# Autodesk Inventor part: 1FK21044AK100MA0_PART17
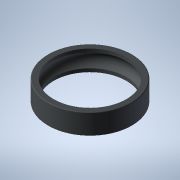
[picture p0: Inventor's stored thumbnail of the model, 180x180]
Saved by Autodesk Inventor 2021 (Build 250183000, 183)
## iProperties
Created: 2025-04
Part Number: 1FK21044AK100MA0_PART17
Material: Generic
Catalog Web Link: www.3dfindit.com
Description: -Servo synchronous motor
Document SubType Name: Modeling
Designer: psAdmin
Mass: 1.64389 g
Surface Area: 26.4305 cm^2
Volume: 1.64389 cm^3
Density: 1 g/cm^3
Appearance: PSOLRGB-212-217-219
Category: PARTsolutions
Title: 1FK21044AK100MA0_PART17
Author: Cadenas PARTsolutions
Comments: Servo synchronous motor
Sending System: PARTsolutions
Preprocessor: ST-DEVELOPER v19.3
PSOL_IDENT_0: {$CADENAS_DATA/23d-libs/siemens_ag/_cat_/5e/d8/1fk21044ak100ma0.prj},216 {VTYP=3D},{NB=1FK21044AK100
PSOL_IDENT_1: MA0_PART17},{LINA=1FK21044AK100MA0_PART17},{NN=1FK21044AK100MA0_PART17},{NOPRJ=TRUE},{DATE=19.08.202
PSOL_IDENT_2: 5 14:00:41},{GEOMDATE=30.07.2025 02:00:53},{VERSION=},{LINEID=10},{WBVAR=},{WBNUMERIC=}  {NB=1FK2104
PSOL_IDENT_3: 4AK100MA0_PART17},{LINA=1FK21044AK100MA0_PART17},{KT=DUMMY},{PREVIEW=../../../_pool_/cb/72/p_d211_xx
PSOL_IDENT_4: _00434j.png},{DESCSHORT=SIMOTICS S-1FK2 HD, SINAMICS S210 3AC 400V-480V, 0.95 Nm, 6000 rpm},{DESCLON
PSOL_IDENT_5: G=SIMOTICS S-1FK2 HD servo motor M0=1.27 Nm; PN = 0.6 kW at nN=6000 rpm (380-480 V); PN = 0.4 kW at
PSOL_IDENT_6: nN=3000 rpm (200-240 V); with holding brake; degree of protection IP64; cylindrical shaft D19x40mm;
PSOL_IDENT_7: absolute encoder 22-bit + 12-bit multiturn (encoder AM22DQC); with OCC interface; plug size M17, rot
PSOL_IDENT_8: atable; SIMOTICS S-1FK2 servomotorfor a wide range of uses in industrial environments. SIMOTICS S‑1F
PSOL_IDENT_9: K2 servomotors are compact synchronous motors with a high dynamic performance that set themselves ap
PSOL_IDENT_10: art as a result of their high power density, degree of protection and overload capability. The motor
PSOL_IDENT_11: s are available in two variants: as High Dynamic variant (highest dynamic performance as a result of
PSOL_IDENT_12: the low intrinsic moment of inertia for applications demanding a high dynamic performance with low
PSOL_IDENT_13: moved masses) - and as Compact variant (precise and stable closed-loop control for medium up to larg
PSOL_IDENT_14: e moved masses as a result of a medium intrinsic moment of inertia). SIMOTICSS‑1FK2 servomotors full
PSOL_IDENT_15: y exploit their strengths in a system with the SINAMICSS210 frequency converter and simple connectio
PSOL_IDENT_16: n using the one cable connection (OCC). Advantages include the short control and positioning times,
PSOL_IDENT_17: fast and precise correction of disturbing quantities as well as stable control with a high dynamic p
PSOL_IDENT_18: erformance. The servo motors can be configured to address a wide range of requirements. For example
PSOL_IDENT_19: with and without holding brake, IP64 or IP65 degree of protection, singleturn or multiturn absolute
PSOL_IDENT_20: encoders - to name just a few. Further, the servomotors are available in different shaft heights ext
PSOL_IDENT_21: ending from 20 to 100. A shaft sealing ring is available to achieve an IP65 degree of protection and
PSOL_IDENT_22: for subsequent mounting at the motor or as spare part. SIMOTICS - the optimum motor for each and ev
PSOL_IDENT_23: ery motion control application.},{INTNO=804766910005},{SUPPLIERALTNO=1FK2104-4AK10-0MA0},{MANUID=1FK
PSOL_IDENT_24: 21044AK100MA0},{MANUNAME=Siemens},{MANUTYPEDESC=Synchronous motor 1FK2-HD 1,27 Nm},{AAU732=SIMOTICS}
PSOL_IDENT_25: ,{AAO057=S-1FK2},{AAU734=SIMOTICS S-1FK2 HD servo motor M0=1.27 Nm; PN = 0.6 kW at nN=6000 rpm (380-
PSOL_IDENT_26: 480 V); PN = 0.4 kW at nN=3000 rpm (200-240 V); with holding brake; degree of protection IP64; cylin
PSOL_IDENT_27: drical shaft D19x40mm; absolute encoder 22-bit + 12-bit multiturn (encoder AM22DQC); with OCC interf
PSOL_IDENT_28: ace; plug size M17, rotatable;},{AAW338=Synchronous motor 1FK2-HD 1,27 Nm},{AAO742=SIMOTICS},{AAO663=
PSOL_IDENT_29: 4042948691076},{NOCUPEROU=1},{PRICEQUANTITY=1},{QUANTITYMIN=1},{QUANTITYINT=1},{CTN=85015100},{COO=D
PSOL_IDENT_30: E},{AAO676=1FK2104-4AK10-0MA0},{AAO677=Siemens AG},{ORDERUNIT=C62},{CONTENTUNIT=C62}
NB: 1FK21044AK100MA0_PART17
NT: Servo synchronous motor
NBSYN: $MANUID._PART17
LINA: 1FK21044AK100MA0_PART17
CATALOG: SIEMENS
PREVIEW: ../../../_pool_/cb/72/p_d211_xx_00434j.png
DESCSHORT: SIMOTICS S-1FK2 HD, SINAMICS S210 3AC 400V-480V, 0.95 Nm, 6000 rpm
DESCLONG: SIMOTICS S-1FK2 HD servo motor M0=1.27 Nm; PN = 0.6 kW at nN=6000 rpm (380-480 V); PN = 0.4 kW at nN=3000 rpm (200-240 V); with holding brake; degree of protect
INTNO: 804766910005
SUPPLIERALTNO: 1FK2104-4AK10-0MA0
MANUID: 1FK21044AK100MA0
MANUNAME: Siemens
MANUTYPEDESC: Synchronous motor 1FK2-HD 1,27 Nm
AAU732: SIMOTICS
AAO057: S-1FK2
AAU734: SIMOTICS S-1FK2 HD servo motor M0=1.27 Nm; PN = 0.6 kW at nN=6000 rpm (380-480 V); PN = 0.4 kW at nN=3000 rpm (200-240 V); with holding brake; degree of protect
AAW338: Synchronous motor 1FK2-HD 1,27 Nm
AAO742: SIMOTICS
AAO663: 4042948691076.0
NOCUPEROU: 1
PRICEQUANTITY: 1
QUANTITYMIN: 1
QUANTITYINT: 1
CTN: 85015100
COO: DE
ARTICLENO: 1FK21044AK100MA0_PART17
BOMINFO: 1FK21044AK100MA0_PART17
CREATOR: CADENAS GmbH
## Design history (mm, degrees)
feature "2025_04_17_15_35_41_0968"
body "Solid1"
